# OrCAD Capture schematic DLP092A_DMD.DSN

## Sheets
1 P04 - IMPORTANT NOTICE
2 P03 - DMD INTERFACE: size D
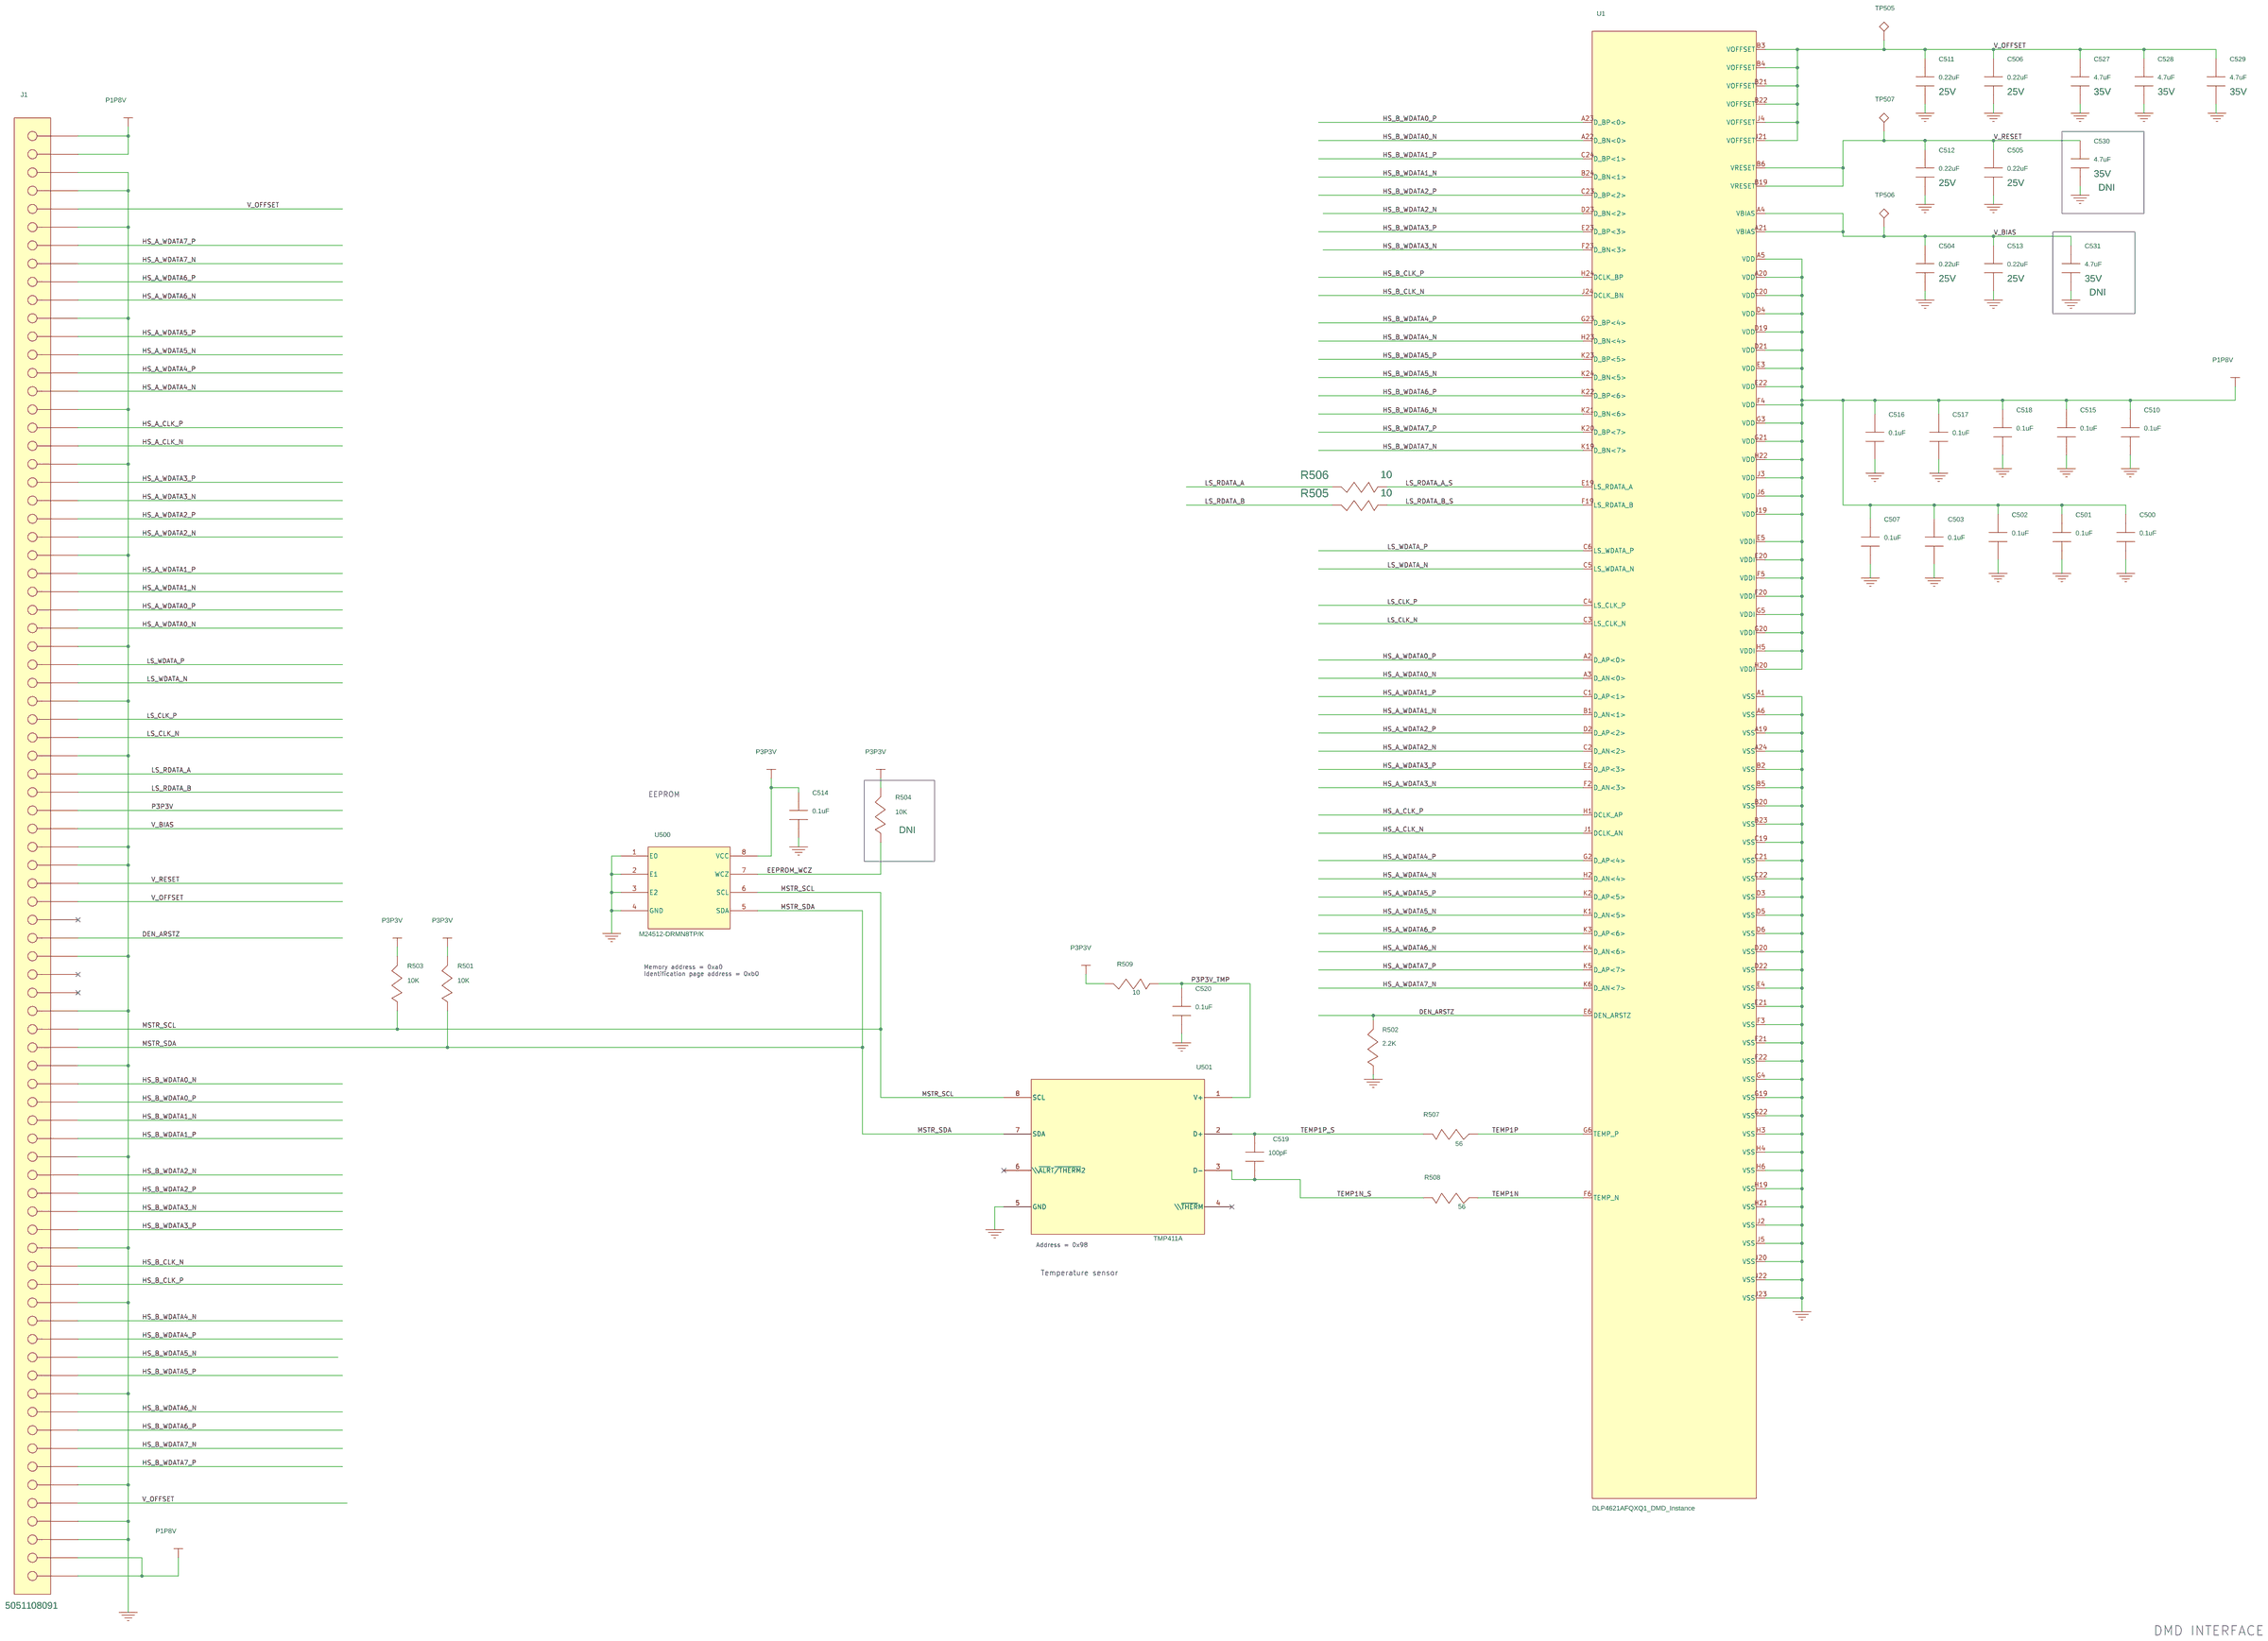
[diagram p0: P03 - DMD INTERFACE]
3 P01 - TITLE PAGE
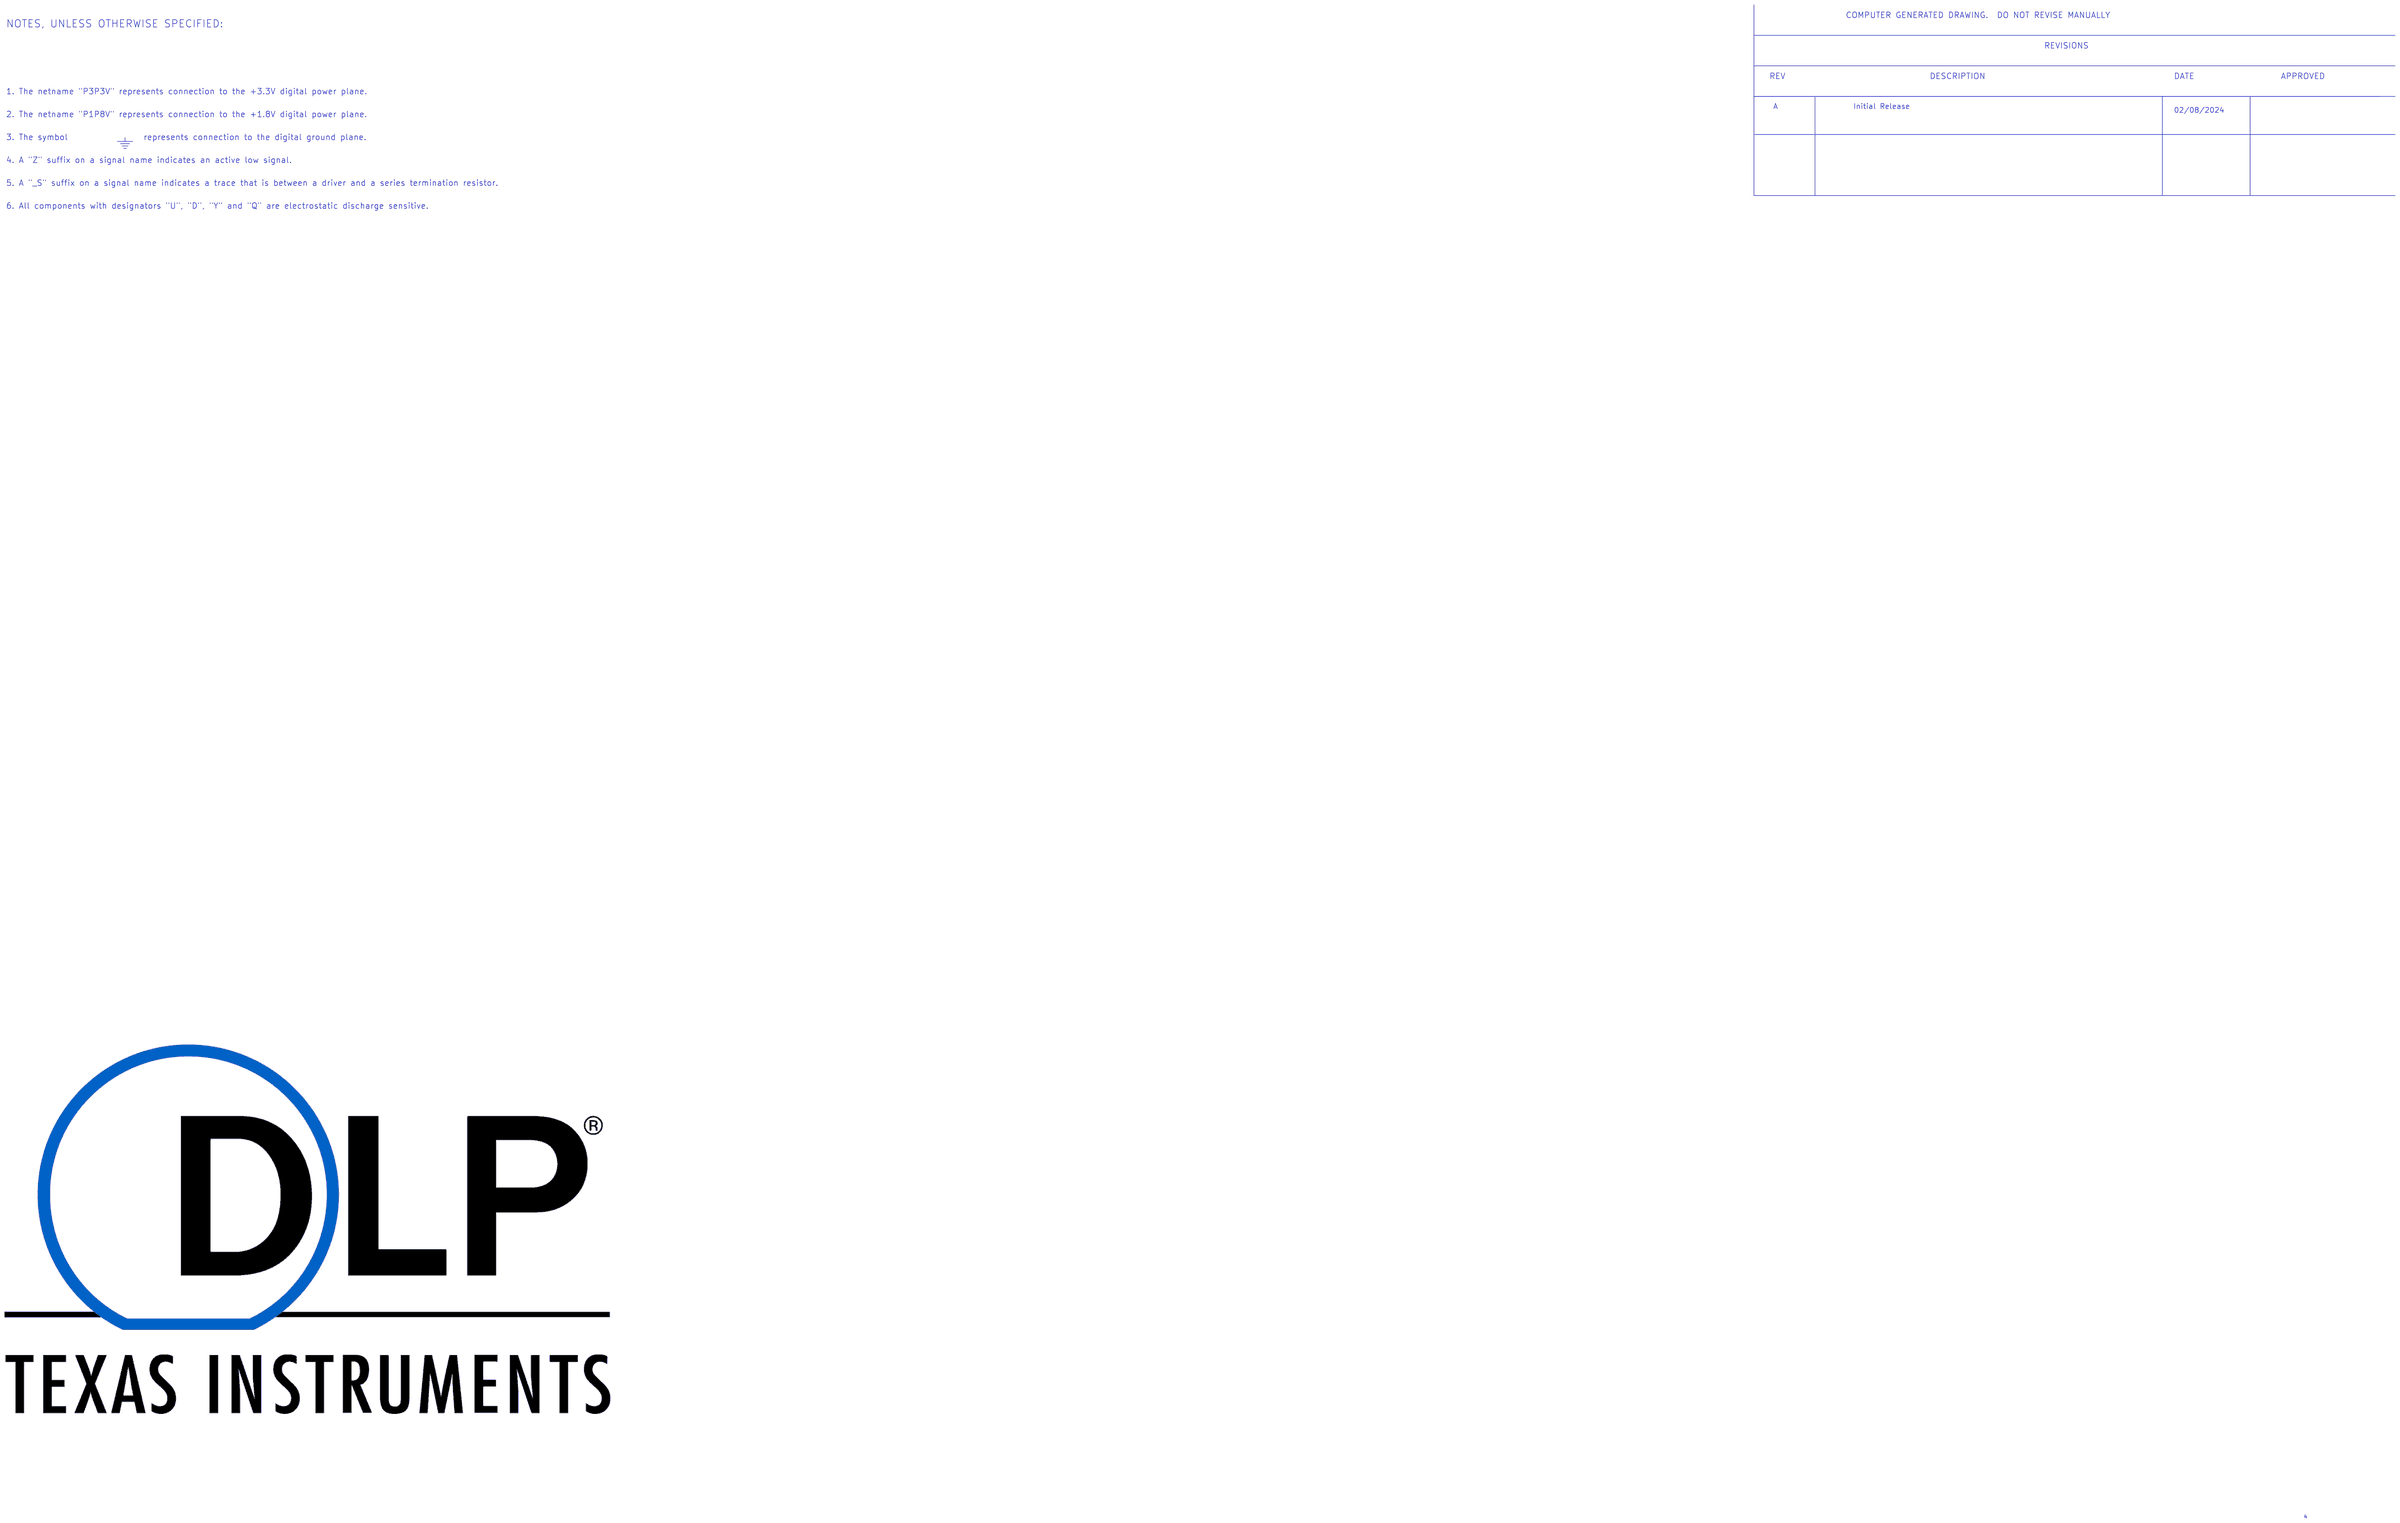
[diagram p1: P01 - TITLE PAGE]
4 P02 - BLOCK_DIAGRAM
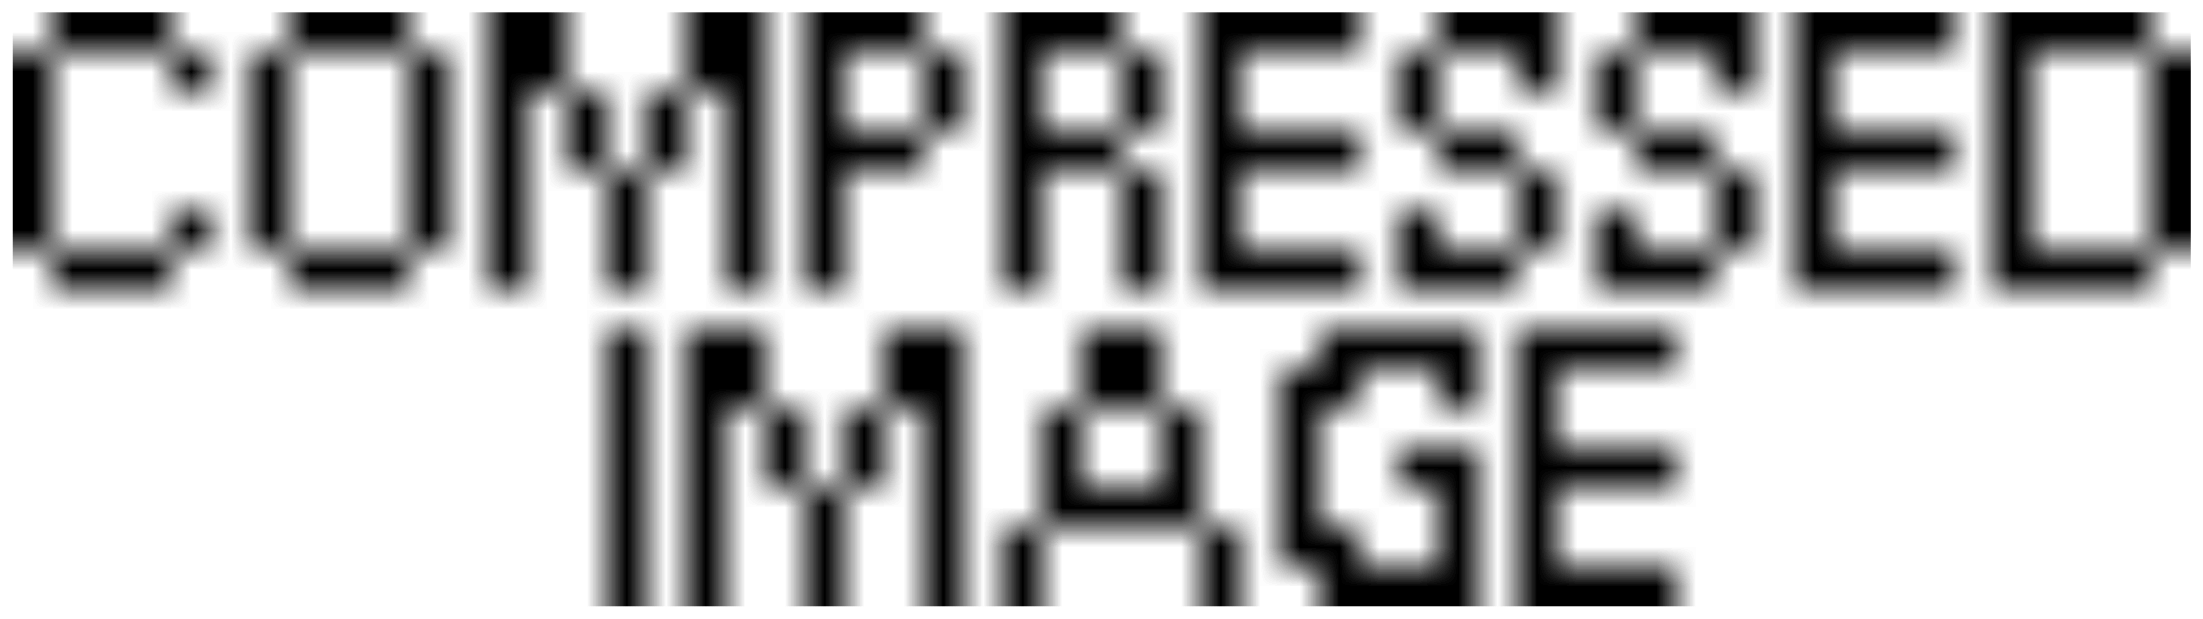
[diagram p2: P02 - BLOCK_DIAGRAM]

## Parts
C500  0.1uF  [0402]
C501  0.1uF  [0402]
C502  0.1uF  [0402]
C503  0.1uF  [0402]
C504  0.22uF  [0603]
C505  0.22uF  [0603]
C506  0.22uF  [0603]
C507  0.1uF  [0402]
C510  0.1uF  [0402]
C511  0.22uF  [0603]
C512  0.22uF  [0603]
C513  0.22uF  [0603]
C514  0.1uF  [0402]
C515  0.1uF  [0402]
C516  0.1uF  [0402]
C517  0.1uF  [0402]
C518  0.1uF  [0402]
C519  100pF  [0402]
C520  0.1uF  [0402]
C527  4.7uF  [0603]
C528  4.7uF  [0603]
C529  4.7uF  [0603]
C530  4.7uF  [0603]
C531  4.7uF  [0603]
J1  5051108091  [CONN80-ZIF-FFC-505110_MLX]
R501  10K  [0402]
R502  2.2K  [0402]
R503  10K  [0402]
R504  10K  [0402]
R505  10  [0402]
R506  10  [0402]
R507  56  [0402]
R508  56  [0402]
R509  10  [0402]
TP505  TP, 36mil Dia  [TP141H91]
TP506  TP, 36mil Dia  [TP141H91]
TP507  TP, 36mil Dia  [TP141H91]
U1  DLP4621AFQXQ1_DMD_Instance  [SKT_2518197]
U500  M24512-DRMN8TP/K  [SOIC8]
U501  TMP411A  [SOIC8-DGK_TI]

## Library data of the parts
C500-C503 C507 C510 C514-C518 C520 = CAP_NP_dsize: CAP CER .1UF 16V X7R 0402; AEC: AEC-Q200; Manuf Part Number: GCM155R71C104KA55D; Manufacturer: Murata; Temp: -55C to 125C; Tolerance: 10%; VPC: 16V
C504-C506 C511-C513 = CAP_NP_dsize: CAP 0.22UF 25V  CERAMIC X7R 0603; AEC: AEC-Q200; Manuf Part Number: GCM188R71E224KA55D; Manufacturer: Murata; Temp: -55C to 125C; Tolerance: 10%; VPC: 25V
C519 = CAP_NP_dsize: CAP CER 100PF 50V 5% NP0 0402; AEC: AEC-Q200; Manuf Part Number: GCM1555C1H101JA16D; Manufacturer: Murata; Temp: -55C to 125C; Tolerance: 5%; VPC: 50V
C527-C529 = CAP_NP_dsize: CAP 4.7UF 35V  CERAMIC X5R 0603; AEC: AEC-Q200; Manuf Part Number: CL10A475KL8NRNC; Manufacturer: Samsung Electro-Mechanics; Temp: -55C to 85C; Tolerance: 10%; VPC: 35V
C530 C531 = CAP_NP_dsize: CAP 4.7UF 35V  CERAMIC X5R 0603; AEC: AEC-Q200; DNI: DNI; Manuf Part Number: CL10A475KL8NRNC; Manufacturer: Samsung Electro-Mechanics; Temp: -55C to 85C; Tolerance: 10%; VPC: 35V
J1 = EM,HDR,80P,1R,2x: CONN FFC/FPC BOTTOM 80 POS 0.5MM; Manufacturer: Molex; Temp: -40C to 105C
R501 R503 = RESISTOR_dsize: RES 10K OHM 1/10W 5% 0402 SMD; AEC: AEC-Q200; ICA_MFR_NAME: PANASONIC; ICA_PARTNUM: $$1784360$$ERJ-3GSYJ103; Manuf Part Number: ERJ-2GEJ103X; Manufacturer: Panasonic; TOLERANCE: 5%; Temp: -55C to 155C; VPC: 1/10W
R502 = RESISTOR_dsize: RES 2.2K OHM 1/10W 5% 0402 SMD; AEC: AEC-Q200; Manuf Part Number: ERJ-2GEJ222X; Manufacturer: Panasonic; Temp: -55C to 155C; Tolerance: 5%; VPC: 1/10W
R504 = RESISTOR_dsize: RES 10K OHM 1/10W 5% 0402 SMD; AEC: AEC-Q200; DNI: DNI; ICA_MFR_NAME: PANASONIC; ICA_PARTNUM: $$1784360$$ERJ-3GSYJ103; Manuf Part Number: ERJ-2GEJ103X; Manufacturer: Panasonic; TOLERANCE: 5%; Temp: -55C to 155C; VPC: 1/10W
R505 = RESISTOR_dsize: RES 10 OHM 1/10W 1% 0402 SMD; AEC: AEC-Q200; Manuf Part Number: ERJ-2RKF10R0X; Manufacturer: Panasonic; TOLERANCE: 1%; Temp: -55C to 155C; VPC: 1/10W
R506 = RESISTOR_dsize: RES 10 OHM 1/10W 1% 0402 SMD; AEC: AEC-Q200; Manuf Part Number: ERJ-2RKF10R0X; Manufacturer: Panasonic; TEMP: -55C to 155C; TOLERANCE: 1%; VPC: 1/10W
R507 R508 = RESISTOR_dsize: RES 56 OHM 1/10W 5% 0402 SMD; AEC: AEC-Q200; Manuf Part Number: ERJ-2GEJ560X; Manufacturer: Panasonic; Temp: -55C to 155C; Tolerance: 5%; VPC: 1/10W
R509 = RESISTOR_dsize: RES 10 OHM 1/10W 1% 0402 SMD; AEC: AEC-Q200; Manuf Part Number: ERJ-2RKF10R0X; Manufacturer: Panasonic; Temp: -55C to 155C; Tolerance: 1%; VPC: 1/10W
TP505-TP507 = EM,TERM,TESTPOINT: TEST POINT; Manuf Part Number: -- NOT A PART --
U1 = DLP462x: IC 0.46 DMD 960x960; DNI: DNI; Manuf Part Number: DLP4621AFQXQ1; Manufacturer: Texas Instruments; Temp: -40C to 105C
U500 = M24C64: IC EEPROM I2C 512Kbit; Manufacturer: STMicro; Temp: -40C to 105C
U501 = TMP411: IC TEMP SENSOR 1 CHANNEL 8-SOIC; AEC: AEC-Q100; Manuf Part Number: TMP411AQDGKRQ1; Manufacturer: Texas Instruments; Temp: -40C to 125C

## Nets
GND: C500.2 C501.2 C502.2 C503.2 C504.2 C505.2 C506.2 C507.2 C510.2 C511.2 C512.2 C513.2 C514.2 C515.2 C516.2 C517.2 C518.2 C520.2 C527.2 C528.2 C529.2 C530.2 C531.2 J1.3 J1.4 J1.6 J1.11 J1.16 J1.19 J1.24 J1.29 J1.32 J1.35 J1.40 J1.41 J1.46 J1.49 J1.52 J1.57 J1.62 J1.65 J1.70 J1.75 J1.77 J1.78 R502.2 U1.A1(VSS) U1.A6(VSS) U1.A19(VSS) U1.A24(VSS) U1.B2(VSS) U1.B5(VSS) U1.B20(VSS) U1.B23(VSS) U1.C19(VSS) U1.C21(VSS) U1.C22(VSS) U1.D3(VSS) U1.D5(VSS) U1.D6(VSS) U1.D20(VSS) U1.D22(VSS) U1.E4(VSS) U1.E21(VSS) U1.F3(VSS) U1.F21(VSS) U1.F22(VSS) U1.G4(VSS) U1.G19(VSS) U1.G22(VSS) U1.H3(VSS) U1.H4(VSS) U1.H6(VSS) U1.H19(VSS) U1.H21(VSS) U1.J2(VSS) U1.J5(VSS) U1.J20(VSS) U1.J22(VSS) U1.J23(VSS) U500.1(E0) U500.2(E1) U500.3(E2) U500.4(GND) U501.5(GND)
DEN_ARSTZ: J1.45 R502.1 U1.E6(DEN_ARSTZ)
EEPROM_WCZ: R504.2 U500.7(WCZ)
HS_A_CLK_N: J1.18 U1.J1(DCLK_AN)
HS_A_CLK_P: J1.17 U1.H1(DCLK_AP)
HS_A_WDATA0_N: J1.28 U1.A3(D_AN<0>)
HS_A_WDATA0_P: J1.27 U1.A2(D_AP<0>)
HS_A_WDATA1_N: J1.26 U1.B1(D_AN<1>)
HS_A_WDATA1_P: J1.25 U1.C1(D_AP<1>)
HS_A_WDATA2_N: J1.23 U1.C2(D_AN<2>)
HS_A_WDATA2_P: J1.22 U1.D2(D_AP<2>)
HS_A_WDATA3_N: J1.21 U1.F2(D_AN<3>)
HS_A_WDATA3_P: J1.20 U1.E2(D_AP<3>)
HS_A_WDATA4_N: J1.15 U1.H2(D_AN<4>)
HS_A_WDATA4_P: J1.14 U1.G2(D_AP<4>)
HS_A_WDATA5_N: J1.13 U1.K1(D_AN<5>)
HS_A_WDATA5_P: J1.12 U1.K2(D_AP<5>)
HS_A_WDATA6_N: J1.10 U1.K4(D_AN<6>)
HS_A_WDATA6_P: J1.9 U1.K3(D_AP<6>)
HS_A_WDATA7_N: J1.8 U1.K6(D_AN<7>)
HS_A_WDATA7_P: J1.7 U1.K5(D_AP<7>)
HS_B_CLK_N: J1.63 U1.J24(DCLK_BN)
HS_B_CLK_P: J1.64 U1.H24(DCLK_BP)
HS_B_WDATA0_N: J1.53 U1.A22(D_BN<0>)
HS_B_WDATA0_P: J1.54 U1.A23(D_BP<0>)
HS_B_WDATA1_N: J1.55 U1.B24(D_BN<1>)
HS_B_WDATA1_P: J1.56 U1.C24(D_BP<1>)
HS_B_WDATA2_N: J1.58 U1.D23(D_BN<2>)
HS_B_WDATA2_P: J1.59 U1.C23(D_BP<2>)
HS_B_WDATA3_N: J1.60 U1.F23(D_BN<3>)
HS_B_WDATA3_P: J1.61 U1.E23(D_BP<3>)
HS_B_WDATA4_N: J1.66 U1.H23(D_BN<4>)
HS_B_WDATA4_P: J1.67 U1.G23(D_BP<4>)
HS_B_WDATA5_N: J1.68 U1.K24(D_BN<5>)
HS_B_WDATA5_P: J1.69 U1.K23(D_BP<5>)
HS_B_WDATA6_N: J1.71 U1.K21(D_BN<6>)
HS_B_WDATA6_P: J1.72 U1.K22(D_BP<6>)
HS_B_WDATA7_N: J1.73 U1.K19(D_BN<7>)
HS_B_WDATA7_P: J1.74 U1.K20(D_BP<7>)
LS_CLK_N: J1.34 U1.C3(LS_CLK_N)
LS_CLK_P: J1.33 U1.C4(LS_CLK_P)
LS_RDATA_A: J1.36 R506.1
LS_RDATA_A_S: R506.2 U1.E19(LS_RDATA_A)
LS_RDATA_B: J1.37 R505.1
LS_RDATA_B_S: R505.2 U1.F19(LS_RDATA_B)
LS_WDATA_N: J1.31 U1.C5(LS_WDATA_N)
LS_WDATA_P: J1.30 U1.C6(LS_WDATA_P)
MSTR_SCL: J1.50 R503.2 U500.6(SCL) U501.8(SCL)
MSTR_SDA: J1.51 R501.2 U500.5(SDA) U501.7(SDA)
P1P8V: C500.1 C501.1 C502.1 C503.1 C507.1 C510.1 C515.1 C516.1 C517.1 C518.1 J1.1 J1.2 J1.79 J1.80 U1.A5(VDD) U1.A20(VDD) U1.C20(VDD) U1.D4(VDD) U1.D19(VDD) U1.D21(VDD) U1.E3(VDD) U1.E5(VDDI) U1.E20(VDDI) U1.E22(VDD) U1.F4(VDD) U1.F5(VDDI) U1.F20(VDDI) U1.G3(VDD) U1.G5(VDDI) U1.G20(VDDI) U1.G21(VDD) U1.H5(VDDI) U1.H20(VDDI) U1.H22(VDD) U1.J3(VDD) U1.J6(VDD) U1.J19(VDD)
P3P3V: C514.1 J1.38 R501.1 R503.1 R504.1 R509.1 U500.8(VCC)
P3P3V_TMP: C520.1 R509.2 U501.1(V+)
TEMP1N: R508.1 U1.F6(TEMP_N)
TEMP1N_S: C519.2 R508.2 U501.3(D-)
TEMP1P: R507.1 U1.G6(TEMP_P)
TEMP1P_S: C519.1 R507.2 U501.2(D+)
V_BIAS: C504.1 C513.1 C531.1 J1.39 TP506.1(P1) U1.A4(VBIAS) U1.A21(VBIAS)
V_OFFSET: C506.1 C511.1 C527.1 C528.1 C529.1 J1.5 J1.43 J1.76 TP505.1(P1) U1.B3(VOFFSET) U1.B4(VOFFSET) U1.B21(VOFFSET) U1.B22(VOFFSET) U1.J4(VOFFSET) U1.J21(VOFFSET)
V_RESET: C505.1 C512.1 C530.1 J1.42 TP507.1(P1) U1.B6(VRESET) U1.B19(VRESET)

Not connected (* = marked no-connect by the designer): J1 44* 47* 48*; U501 4(\\~{THER}M)* 6(\\~{ALR}T~{/THERM}2)*

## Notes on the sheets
sheet 2
- EEPROM
- Memory address = 0xa0
  Identification page address = 0xb0
- Address = 0x98
- Temperature sensor
- DMD INTERFACE
sheet 3
- COMPUTER GENERATED DRAWING.  DO NOT REVISE MANUALLY
- NOTES, UNLESS OTHERWISE SPECIFIED:
- REVISIONS
- REV
- DESCRIPTION
- DATE
- APPROVED
- 1. The netname "P3P3V" represents connection to the +3.3V digital power plane.
- A
- Initial Release
- 2. The netname "P1P8V" represents connection to the +1.8V digital power plane.
- 02/08/2024
- 3. The symbol
- represents connection to the digital ground plane.
- 4. A "Z" suffix on a signal name indicates an active low signal.
- 5. A "_S" suffix on a signal name indicates a trace that is between a driver and a series termination resistor.
- 6. All components with designators "U", "D", "Y" and "Q" are electrostatic discharge sensitive.
- 4
